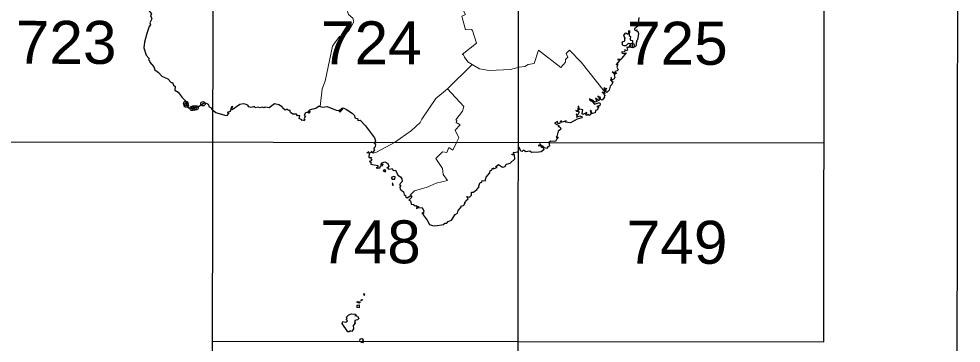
# Model space of a CAD drawing. Extents: x 487425 to 492029, y 4383576 to 4386788.
# Drawn here: x 491602 to 492029.3, y 4385465.2 to 4385612.4 of the extents above; entities that cross this region are included whole.
import ezdxf
from ezdxf.enums import TextEntityAlignment as Align

# ---------------------------------------------------------------- set-up
doc = ezdxf.new("R2010")
doc.units = 0
doc.header["$LTSCALE"] = 4
doc.header["$PDMODE"] = 32
doc.header["$PDSIZE"] = 2
doc.linetypes.add('DOTTED', pattern=[1.5, 0.3, -1.2])
for name, color, linetype, lineweight in [('1', 7, 'Continuous', 13), ('2', 7, 'DOTTED', 13), ('3', 7, 'Continuous', 25)]:
    doc.layers.add(name, color=color, linetype=linetype, lineweight=lineweight)

msp = doc.modelspace()

# ---------------------------------------------------------------- linework, layer by layer
at = {"layer": '1', "lineweight": 25}
for p, q in [((491689.72, 4385375.83), (491690.51, 4385917.78)), ((491828.28, 4385375.63), (491829.07, 4385917.58)), ((491966.97, 4385465.74), (491967.63, 4385917.38)), ((491412.87, 4385556.87), (491967.1, 4385556.07)), ((491689.85, 4385466.14), (491966.97, 4385465.74))]:
    msp.add_line(p, q, dxfattribs=at)
msp.add_lwpolyline([(487429.26, 4386787.97), (492029.26, 4386781.28), (492024.61, 4383576.28), (487424.61, 4383582.97)], close=True, dxfattribs=at)
at = {"layer": '3', "lineweight": 13}
msp.add_line((491807.53, 4385591.7), (491796.33, 4385580.65), dxfattribs=at)
for points in [[(491792.42, 4385632.74), (491802.13, 4385619.04), (491804.51, 4385614.3), (491802.84, 4385613.6), (491804.51, 4385607.39), (491807.29, 4385607.56), (491807.73, 4385607.06), (491809.53, 4385601.4)], [(491750.99, 4385626.23), (491749.14, 4385625.23), (491748.41, 4385622), (491749.32, 4385617.84), (491749.91, 4385617.74), (491750.77, 4385616.8), (491751.49, 4385614.41), (491753.52, 4385612.74), (491753.96, 4385611.06), (491751.87, 4385607.25), (491749.76, 4385605.19), (491747.46, 4385604.39), (491745.31, 4385601.48)], [(491738.6, 4385572.56), (491739.49, 4385580.59), (491740.86, 4385584.09), (491744.29, 4385600), (491745.31, 4385601.48)], [(491807.53, 4385591.7), (491805.61, 4385592.92), (491804.02, 4385594.92), (491803.7, 4385596.03), (491803.09, 4385596.15), (491809.53, 4385601.4)], [(491828.82, 4385590.48), (491831.46, 4385590.77), (491832.92, 4385591.62), (491835.69, 4385592.14), (491837.6, 4385598.18), (491847.74, 4385590.37), (491849.87, 4385592.65), (491849.9, 4385593.94), (491850.91, 4385595.05), (491850.2, 4385596.65), (491851.67, 4385598.23), (491857.03, 4385592.7), (491867.42, 4385579.5)], [(491807.53, 4385591.7), (491810.84, 4385589.77), (491815.3, 4385588.98), (491824.89, 4385589.46), (491828.82, 4385590.48)], [(491796.33, 4385580.65), (491791.09, 4385576.28), (491784.67, 4385566.78), (491784.02, 4385565.27), (491780, 4385561.78), (491772.37, 4385556.26)], [(491796.33, 4385580.65), (491803.8, 4385572.65), (491803.2, 4385570.5), (491800.22, 4385566.58), (491800.63, 4385566.32), (491800.38, 4385565.38), (491802.1, 4385564.31), (491799.88, 4385561.83), (491801.47, 4385558.43), (491800.47, 4385556.24)], [(491772.37, 4385556.26), (491764.16, 4385551.9), (491762.65, 4385551.36), (491762.54, 4385551.63)], [(491800.47, 4385556.24), (491798.78, 4385552.73), (491796.93, 4385553.94), (491796.06, 4385551.67), (491794.13, 4385552.04), (491791.08, 4385548.96), (491794.05, 4385544.46), (491794.43, 4385541.8), (491796.39, 4385539.08), (491791.2, 4385537.87), (491787.1, 4385535.97), (491781.4, 4385534.34), (491779.65, 4385532.58), (491779.72, 4385532.2)]]:
    msp.add_lwpolyline(points, dxfattribs=at)
at = {"layer": '3'}
for points in [[(491659.92, 4385619.31), (491660.78, 4385618.68), (491660.36, 4385617.88), (491660.9, 4385617.26), (491660.94, 4385616.24), (491662.13, 4385614.67), (491661.78, 4385613.96), (491662.38, 4385612.34), (491661.47, 4385610.57), (491661.73, 4385609.6), (491661.11, 4385608.88), (491660.09, 4385605.73), (491659.03, 4385601.77)], [(491883.06, 4385613.04), (491882.63, 4385609.07), (491881.23, 4385607.85), (491881.17, 4385607.37), (491881.81, 4385607.07), (491882.15, 4385607.35), (491882.08, 4385606.89), (491882.61, 4385606.66), (491883.04, 4385605.75), (491882.58, 4385602.8), (491882.05, 4385602.41), (491882.24, 4385602)], [(491875.63, 4385601.43), (491875.68, 4385601.88), (491876.83, 4385602.37), (491876.74, 4385603.44), (491877.12, 4385603.54), (491876.77, 4385603.63), (491876.34, 4385604.94), (491877.24, 4385606), (491878.2, 4385605.47), (491878.53, 4385605.9), (491878.52, 4385607.16), (491878.91, 4385606.98), (491878.81, 4385604.88), (491879.41, 4385604.33), (491879.22, 4385603.21), (491879.39, 4385602.75), (491880.3, 4385602.6), (491880.27, 4385601.43)], [(491882.24, 4385602), (491881.94, 4385601.91), (491882.02, 4385601.44)], [(491659.03, 4385601.77), (491658.66, 4385599.23), (491659.71, 4385595.87), (491661.1, 4385594.39), (491660.87, 4385593.82), (491661.44, 4385593.21), (491661.28, 4385592.86), (491663.16, 4385590.53), (491663.67, 4385589.24), (491665.36, 4385588.05)], [(491875.63, 4385601.43), (491875.61, 4385600.55), (491876.37, 4385600.24), (491877.4, 4385600.23), (491878.41, 4385601.28), (491879.14, 4385601.13), (491879.39, 4385600.69), (491878.45, 4385599.41), (491877.75, 4385599.45), (491877.93, 4385598.11), (491877.28, 4385597.84), (491876.71, 4385598.42), (491876.72, 4385597.68), (491876.34, 4385597.32), (491875.39, 4385597.4), (491875.36, 4385597.03), (491876.09, 4385596.68), (491877.35, 4385596.95), (491875.36, 4385594.52)], [(491880.27, 4385601.43), (491880.16, 4385599.72), (491880.5, 4385599.44), (491881.73, 4385599.94), (491882.14, 4385600.66), (491882.02, 4385601.44)], [(491875.36, 4385594.52), (491875.05, 4385593.88), (491873.51, 4385593.94), (491874.5, 4385593.59), (491872.82, 4385591.65), (491873.61, 4385592.03), (491873.18, 4385590.52), (491873.72, 4385589.18), (491873.37, 4385588.75), (491872.29, 4385588.56), (491872.35, 4385588.15), (491871.85, 4385587.95), (491871.1, 4385588.28), (491871.87, 4385587.43), (491872.79, 4385587.97), (491872.93, 4385587.7), (491872, 4385587.01), (491872.26, 4385585.83), (491872.01, 4385585.12), (491870.9, 4385584.62), (491870.84, 4385584.88)], [(491665.36, 4385588.05), (491666.8, 4385586.31), (491669.63, 4385585.13), (491671.06, 4385583.45), (491671.63, 4385583.55), (491672.2, 4385582.22), (491672.91, 4385581.72), (491672.76, 4385580.04), (491674.26, 4385579.04), (491676.15, 4385576.74)], [(491870.84, 4385584.88), (491870.53, 4385585.72), (491870.53, 4385584.87), (491870.13, 4385584.7), (491870.59, 4385584.55), (491870.83, 4385583.81), (491871.14, 4385584.17), (491871.35, 4385583.86), (491870.87, 4385582.52), (491870.15, 4385581.86), (491869.69, 4385579.98), (491868.59, 4385578.91), (491868.18, 4385579.42), (491868.39, 4385580.85), (491868, 4385580.27), (491867.59, 4385581.04), (491867.31, 4385580.92), (491867.66, 4385579.91), (491867.42, 4385579.5)], [(491676.15, 4385576.74), (491677.8, 4385575.04), (491678.04, 4385573.26), (491679.1, 4385571.9), (491683.29, 4385572.39), (491686.17, 4385574.38), (491687.83, 4385573.59), (491688.35, 4385572.39), (491689.01, 4385572.21), (491689.66, 4385571.16)], [(491867.42, 4385579.5), (491867.64, 4385578.57), (491866.47, 4385579.06), (491867.86, 4385577.53), (491867.41, 4385577.42), (491867.58, 4385576.88), (491866.49, 4385575.48), (491865.84, 4385575.8), (491865.57, 4385576.95), (491865.18, 4385576.73), (491864.6, 4385577.39), (491865.25, 4385576.02), (491865.01, 4385575.24), (491863.5, 4385576.35), (491864.1, 4385574.9), (491863.17, 4385574.63), (491862.48, 4385575.33)], [(491702.27, 4385573.48), (491698.68, 4385571.03), (491698.44, 4385571.75), (491699.09, 4385572.63), (491698.52, 4385572.4), (491697.78, 4385570.32), (491696.41, 4385569.89), (491697.3, 4385569.56), (491696.23, 4385568.3), (491691.29, 4385569.71), (491689.66, 4385571.16)], [(491721.56, 4385572), (491721.45, 4385572.42), (491719.86, 4385573.41), (491718.01, 4385573.77), (491715.58, 4385571.97), (491713.66, 4385572.35), (491713.19, 4385571.94), (491712.39, 4385572.28), (491711.25, 4385571.94), (491710.57, 4385572.32), (491709.14, 4385572), (491708.91, 4385572.59), (491707.36, 4385572.13), (491706.25, 4385572.51), (491705.88, 4385573.2), (491705.04, 4385573.58), (491703.87, 4385573.78), (491702.27, 4385573.48)], [(491730.38, 4385566.26), (491730.31, 4385566.62), (491729.1, 4385567.15), (491729.42, 4385568.48), (491728.33, 4385568.44), (491727.86, 4385569.16), (491726.22, 4385569.09), (491725.2, 4385569.82), (491724.91, 4385570.9), (491724.28, 4385570.76), (491723.63, 4385571.38), (491722.75, 4385571.01), (491721.56, 4385572)], [(491738.6, 4385572.56), (491737.87, 4385572.6), (491736.94, 4385571.8), (491733.69, 4385570.97), (491733.88, 4385570.44), (491733.37, 4385570.57), (491733.7, 4385570.26), (491733.33, 4385570.41), (491733.56, 4385570.11), (491733.11, 4385570.05), (491733.47, 4385569.8), (491734.1, 4385570.27), (491733.49, 4385569.65), (491732.87, 4385570.06), (491731.78, 4385569.59), (491731.45, 4385568.59), (491731.94, 4385568.27), (491731.42, 4385567.12), (491731.72, 4385566.57), (491731.28, 4385566.05), (491731.12, 4385566.39), (491730.38, 4385566.26)], [(491738.6, 4385572.56), (491739.74, 4385572.23), (491741.82, 4385572.61), (491745.96, 4385570.91), (491746.93, 4385570.85), (491747.59, 4385570.15), (491748.03, 4385570.35), (491747.15, 4385570.93), (491747.63, 4385570.68), (491747.46, 4385570.97), (491747.77, 4385570.79), (491747.6, 4385571.08), (491748.04, 4385571.02), (491748.59, 4385571.87), (491748.79, 4385571.55)], [(491748.79, 4385571.55), (491747.93, 4385570.49), (491749, 4385571.94), (491750.55, 4385571.3), (491753.11, 4385569.56), (491754.18, 4385568.46), (491754.4, 4385567.5), (491755.78, 4385566.97), (491755.78, 4385566.31), (491756.77, 4385566.46), (491759.23, 4385563.83)], [(491861.65, 4385569.94), (491861.73, 4385570.38), (491861.12, 4385570.85), (491861.51, 4385569.26), (491860.71, 4385568.54), (491860.19, 4385568.93), (491859.54, 4385568.58), (491859.11, 4385568.87), (491859.51, 4385569.86), (491857.68, 4385569.03), (491857.38, 4385569.49), (491857.73, 4385571.13), (491856.27, 4385571.44), (491855.98, 4385572.53), (491855.59, 4385572.72), (491855.53, 4385571.12), (491856.01, 4385571.17), (491855.1, 4385570.47), (491854.52, 4385570.83), (491854.8, 4385570.46)], [(491862.48, 4385575.33), (491860.83, 4385576.02), (491860.84, 4385575.25), (491861.11, 4385575.58), (491861, 4385575.1), (491861.47, 4385575.5), (491861.29, 4385575.16), (491861.61, 4385575.43), (491861.61, 4385575.02), (491861.82, 4385575.33), (491861.65, 4385575.01), (491862.34, 4385575.02), (491862.16, 4385574.74), (491863.03, 4385573.67), (491865.32, 4385574.43), (491865.59, 4385573.64), (491865.41, 4385573.1), (491864.08, 4385572.58), (491865.12, 4385572.45), (491864.47, 4385571.9), (491864.39, 4385571.1), (491863.54, 4385570.76), (491863.26, 4385569.79), (491862.18, 4385569.39), (491861.65, 4385569.94)], [(491854.8, 4385570.46), (491855.64, 4385570.55), (491856.07, 4385570.18), (491855.51, 4385568.78), (491854.66, 4385569.08), (491855.11, 4385568.31), (491854.9, 4385567.82), (491856.39, 4385568.39), (491857.49, 4385567.95), (491857.34, 4385567.48), (491855.12, 4385566.92), (491852.12, 4385565.17), (491849.74, 4385565.51), (491850.16, 4385566.16), (491848.18, 4385565.46), (491847.86, 4385565.46), (491848.01, 4385566.12), (491847.82, 4385565.9)], [(491759.23, 4385563.83), (491763.29, 4385558.38), (491763.76, 4385557.01), (491763.47, 4385556.27)], [(491847.82, 4385565.9), (491847.41, 4385565.82), (491847.35, 4385564.88), (491846.36, 4385564.9), (491846.31, 4385565.85), (491844.94, 4385565.07), (491846.87, 4385563.94), (491846.5, 4385563.47), (491846.95, 4385563.54), (491847.79, 4385562.81), (491847.58, 4385562.14), (491846.49, 4385561.47), (491846, 4385559.01), (491845.62, 4385558.74), (491846.52, 4385558.75), (491846, 4385557.99)], [(491762.54, 4385551.63), (491763.36, 4385552.99), (491763, 4385553.69), (491763.75, 4385554.47), (491763.86, 4385555.42), (491763.31, 4385555.79), (491763.47, 4385556.27)], [(491842.25, 4385556.23), (491842.63, 4385554.63), (491841.86, 4385554.3), (491841.45, 4385553.53), (491840.32, 4385553.77), (491839.63, 4385554.63), (491839.13, 4385554.55), (491838.18, 4385555.75), (491838.51, 4385555), (491837.43, 4385554.97), (491838.57, 4385554.89), (491839.02, 4385554.22), (491839.59, 4385554.11), (491840.08, 4385552.86), (491838.85, 4385552.06), (491837.74, 4385551.93)], [(491846, 4385557.99), (491845.28, 4385556.66), (491843.24, 4385556.86), (491842.25, 4385556.23)], [(491762.54, 4385551.63), (491761.71, 4385552.26), (491761.86, 4385551.72), (491760.92, 4385551.35), (491760.7, 4385549.44), (491761.96, 4385549.42), (491761.63, 4385548.86), (491762, 4385548.59), (491761.74, 4385548.01), (491760.86, 4385547.57), (491761.59, 4385547.38), (491761.61, 4385546.44), (491764.81, 4385545.84), (491764.75, 4385545.14), (491764.01, 4385544.79), (491764.57, 4385544.6)], [(491816.39, 4385543.78), (491816.86, 4385544.81), (491817.23, 4385544.28), (491818.72, 4385544.9), (491818.75, 4385545.25), (491818.13, 4385545.29), (491819.49, 4385546.35), (491821.33, 4385545.12), (491822.58, 4385545.41), (491823.01, 4385546.38), (491824.76, 4385546.85), (491826.92, 4385548.88), (491826.82, 4385550.61)], [(491826.82, 4385550.61), (491825.7, 4385550.66), (491825.62, 4385550.98), (491826.42, 4385551.12), (491826.47, 4385551.54), (491826.09, 4385551.69), (491828.36, 4385552.06), (491828.82, 4385554.12)], [(491837.74, 4385551.93), (491834.43, 4385551.69), (491833.73, 4385552.26), (491831.95, 4385552.07), (491830.85, 4385552.76), (491830.25, 4385552.21), (491829.65, 4385552.32), (491828.82, 4385554.12)], [(491764.57, 4385544.6), (491765.65, 4385544.77), (491766.21, 4385545.75), (491766.71, 4385545.66), (491767.21, 4385546.23), (491766.8, 4385546.13), (491766.84, 4385546.54), (491766.22, 4385546.1), (491766.78, 4385547.09), (491767.96, 4385547.42), (491769.25, 4385546.78), (491769.73, 4385545.52), (491769.25, 4385544.98), (491769.53, 4385544.42), (491769.98, 4385544.13), (491771.22, 4385544.49), (491771.78, 4385543.63), (491772.76, 4385543.65)], [(491772.76, 4385543.65), (491773.9, 4385541.5), (491775.14, 4385540.7), (491775.74, 4385539.82), (491775.76, 4385538.5), (491774.64, 4385537.13), (491775.15, 4385536.79), (491774.72, 4385536.03), (491774.91, 4385535.1), (491776.41, 4385533.92), (491776.8, 4385532.63), (491777.43, 4385532.12), (491777.26, 4385531.69), (491778.11, 4385531.15), (491779.72, 4385532.2)], [(491809.71, 4385534.9), (491810.7, 4385536.11), (491810.54, 4385536.64), (491811.15, 4385538.12), (491811.94, 4385538.26), (491812.06, 4385539.05), (491813.38, 4385538.93), (491813.84, 4385540.49), (491815.59, 4385542.49), (491815.78, 4385543.53), (491816.39, 4385543.78)], [(491802.33, 4385526.54), (491802.78, 4385527.43), (491803.73, 4385527.86), (491804.35, 4385528.93), (491804.08, 4385529.05), (491804.67, 4385529.27), (491804.82, 4385529.88), (491805.74, 4385530.66), (491805.15, 4385531.79), (491806.37, 4385531.5), (491807.33, 4385532.4), (491807.25, 4385533.7), (491808.21, 4385533.76), (491809.71, 4385534.9)], [(491779.72, 4385532.2), (491780.25, 4385531.38), (491778.89, 4385530.02), (491779.6, 4385529.73), (491779.95, 4385528.28), (491780.93, 4385528.14), (491781.7, 4385527.46), (491782.27, 4385527.7), (491782.38, 4385527.27), (491783.05, 4385527.27), (491783.31, 4385527.02), (491782.89, 4385526.63), (491784.83, 4385526.81), (491785.71, 4385525.1), (491785.51, 4385524.45), (491784.75, 4385524.03), (491785.44, 4385524.07), (491785.32, 4385523.38), (491787.11, 4385521.09)], [(491787.11, 4385521.09), (491788.27, 4385519.01), (491789.64, 4385518.57), (491790.7, 4385518.37), (491794.69, 4385519.11), (491795.16, 4385519.67), (491796.07, 4385519.66), (491796.64, 4385520.35), (491798.22, 4385521.03), (491799.86, 4385523.57), (491800.94, 4385524.12), (491801.17, 4385525.45), (491802.33, 4385526.54)], [(491753.04, 4385470.53), (491752.11, 4385470.78), (491751.92, 4385470.41), (491751.17, 4385470.38), (491748.66, 4385474.05), (491748.9, 4385475), (491750.3, 4385474.65), (491751.05, 4385475.33), (491750.48, 4385475.88), (491750.84, 4385476.12), (491750.65, 4385477), (491751.61, 4385478.08)], [(491751.61, 4385478.08), (491752.78, 4385478.47), (491754.69, 4385478.32), (491754.94, 4385477.81), (491754.32, 4385477.82), (491755.56, 4385477.4), (491756.11, 4385476.43), (491755.5, 4385475.82), (491754.4, 4385475.53), (491754.7, 4385475.35), (491754.22, 4385475), (491754.57, 4385474.26), (491753.56, 4385473.22), (491753.69, 4385471.74), (491753.04, 4385470.53)], [(491756.59, 4385465.95), (491756.76, 4385467.2), (491757.48, 4385467.3), (491758.08, 4385467.07), (491757.88, 4385466.66), (491758.35, 4385465.96)], [(491758.35, 4385465.96), (491757.84, 4385465.38), (491756.59, 4385465.95)]]:
    msp.add_lwpolyline(points, dxfattribs=at)
for points in [[(491760.65, 4385552.1), (491759.74, 4385551.54), (491760.56, 4385551.7)], [(491767.79, 4385543.88), (491767.26, 4385543.35), (491768.05, 4385542.91), (491768.4, 4385543.34)], [(491768.9, 4385544.84), (491768.86, 4385544.59), (491769.18, 4385544.86)], [(491772.06, 4385540.84), (491770.89, 4385540.44), (491771.29, 4385539.64), (491772.47, 4385539.69), (491772.66, 4385540.66)], [(491771.3, 4385537.69), (491771.53, 4385536.75), (491771.73, 4385537.27), (491771.56, 4385537.87)], [(491782.37, 4385526.67), (491782.38, 4385526.29), (491782.72, 4385526.66)], [(491758.5, 4385487.76), (491758.23, 4385487.24), (491758.78, 4385486.95), (491758.94, 4385487.27)], [(491756.37, 4385482.53), (491756.39, 4385481.26), (491755.2, 4385481.38), (491755.59, 4385481.91), (491755.26, 4385482.37)], [(491755.84, 4385484.09), (491756.97, 4385484), (491756.39, 4385483.32), (491755.32, 4385483.8)], [(491757.42, 4385485.05), (491757.82, 4385484.9), (491757.31, 4385484.46)]]:
    msp.add_lwpolyline(points, close=True, dxfattribs=at)
for p in [(491880.08, 4385600.31), (491677.75, 4385573.94), (491677.93, 4385573.17), (491680.57, 4385571.75), (491681.38, 4385571.91), (491682.4, 4385572.05), (491685.52, 4385573.85)]:
    msp.add_point(p, dxfattribs=at)

# ---------------------------------------------------------------- texts
at = {"layer": '2', "width": 1.05}
for s, p in [('723', (491623.46, 4385591.96)), ('724', (491761.82, 4385591.76)), ('725', (491900.58, 4385591.56)), ('748', (491761.42, 4385501.45)), ('749', (491900.44, 4385501.25))]:
    msp.add_text(s, height=19.5, rotation=359.917, dxfattribs=at).set_placement(p, align=Align.CENTER)

doc.saveas('drawing.dxf')
